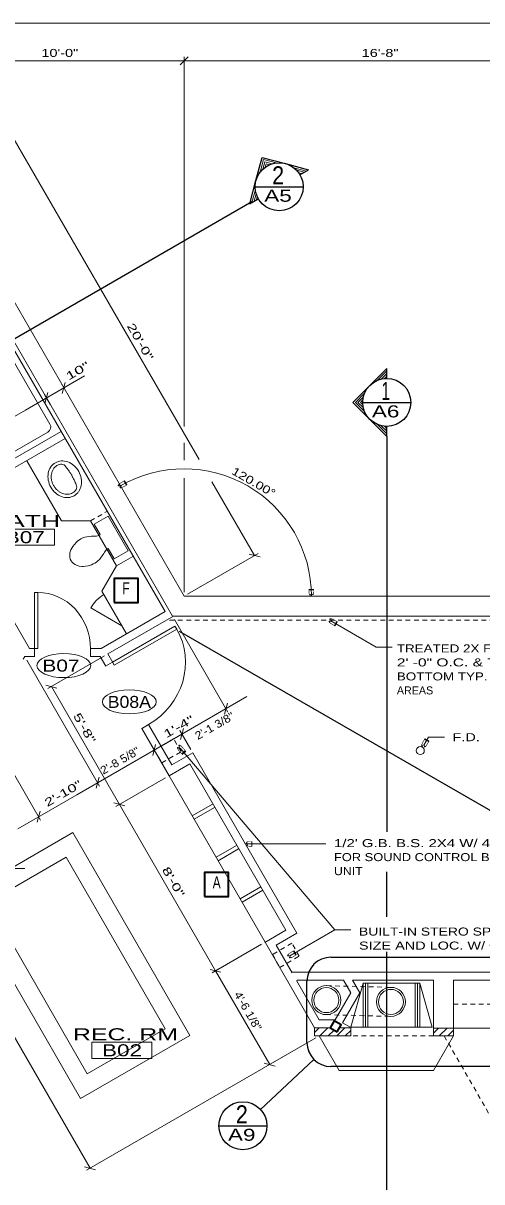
# Model space of a CAD drawing. Extents: x 7 to 126, y 6 to 93.
# Drawn here: x 37.51 to 56.6, y 44.6 to 92.85 of the extents above; entities that cross this region are included whole.
import ezdxf
from ezdxf.enums import TextEntityAlignment as Align

# ---------------------------------------------------------------- set-up
doc = ezdxf.new("R2010")
doc.units = 0
doc.header["$LTSCALE"] = 0.13
doc.linetypes.add('SHORT_DASHED', pattern=[2.7, 1.5, -1.2])
for name, color, linetype, lineweight in [('12', 7, 'Continuous', 35), ('14', 7, 'Continuous', 13), ('15', 7, 'Continuous', 13), ('17', 7, 'Continuous', 13), ('22', 7, 'SHORT_DASHED', 13), ('24', 7, 'Continuous', 13), ('30', 7, 'Continuous', 13), ('34', 7, 'Continuous', 13), ('35', 7, 'Continuous', 13), ('37', 7, 'SHORT_DASHED', 13), ('38', 7, 'Continuous', 13), ('40', 7, 'Continuous', 13), ('42', 7, 'Continuous', 13), ('45', 7, 'Continuous', 13), ('50', 7, 'Continuous', 13), ('53', 7, 'Continuous', 13), ('55', 7, 'Continuous', 13), ('56', 7, 'Continuous', 13), ('7', 7, 'Continuous', 13)]:
    doc.layers.add(name, color=color, linetype=linetype, lineweight=lineweight)

msp = doc.modelspace()

# ---------------------------------------------------------------- linework, layer by layer
at = {"layer": '12'}
msp.add_lwpolyline([(50.5834, 50.8466), (50.7501, 51.1353), (50.4615, 51.302), (50.2948, 51.0133)], close=True, dxfattribs=at)
msp.add_lwpolyline([(50.5834, 50.8466), (50.7501, 51.1353), (50.4615, 51.302), (50.2948, 51.0133)], close=True, dxfattribs=at)
msp.add_lwpolyline([(50.5834, 50.8466), (50.7501, 51.1353), (50.4615, 51.302), (50.2948, 51.0133)], close=True, dxfattribs=at)
msp.add_lwpolyline([(50.5834, 50.8466), (50.7501, 51.1353), (50.4615, 51.302), (50.2948, 51.0133)], close=True, dxfattribs=at)
at = {"layer": '14'}
msp.add_lwpolyline([(115.8724, 34.3511), (77.539, 34.3511), (75.8724, 37.2379), (59.2057, 37.2379), (57.539, 34.3511), (40.8724, 34.3511), (16.7057, 76.209), (22.539, 86.3127), (34.2057, 86.3127), (44.2057, 68.9922), (60.8724, 68.9922)], dxfattribs=at)
at = {"layer": '15'}
msp.add_lwpolyline([(23.2126, 85.4793), (33.7246, 85.4793), (43.7246, 68.1588), (60.3912, 68.1588), (63.7246, 62.3853)], dxfattribs=at)
at = {"layer": '17'}
for points in [[(37.9761, 66.811), (38.122, 66.811), (38.122, 69.1444), (37.9761, 69.1444)], [(41.231, 66.2432), (41.3039, 66.1169), (43.902, 67.6169), (43.8291, 67.7432)]]:
    msp.add_lwpolyline(points, close=True, dxfattribs=at)
for centre, major_axis, ratio, start_param, end_param in [((38.122, 66.811), (0, 2.3333), 0.9375, 4.7123888, 6.2831852), ((41.3039, 66.1169), (2.5981, 1.5), 0.951389, 4.712389, 6.2831853)]:
    msp.add_ellipse(centre, major_axis=major_axis, ratio=ratio, start_param=start_param, end_param=end_param, dxfattribs=at)
at = {"layer": '22'}
msp.add_line((55.0345, 50.6771), (61.6389, 39.2379), dxfattribs=at)
at = {"layer": '24'}
msp.add_line((36.5897, 80.1835), (43.423, 68.3478), dxfattribs=at)
at = {"layer": '24', "linetype": 'SHORT_DASHED'}
msp.add_line((60.295, 67.9922), (43.4737, 67.9922), dxfattribs=at)
at = {"layer": '30'}
for p, q in [((36.9987, 78.9763), (38.6238, 76.1617)), ((38.5323, 75.8202), (37.0889, 74.9869))]:
    msp.add_line(p, q, dxfattribs=at)
msp.add_lwpolyline([(41.0446, 72.3211), (40.4673, 71.9877), (40.7173, 71.5547), (40.6555, 71.516), (40.5644, 71.4913), (40.4501, 71.4966), (40.3605, 71.4934), (40.2543, 71.4824), (40.1564, 71.4642), (40.0776, 71.4445), (39.9984, 71.416), (39.913, 71.378), (39.8509, 71.3381), (39.7873, 71.291), (39.7118, 71.2243), (39.6407, 71.1488), (39.5749, 71.0632), (39.5303, 70.9901), (39.4976, 70.9221), (39.4575, 70.7905), (39.4482, 70.6755), (39.4537, 70.6152), (39.4727, 70.5385), (39.5047, 70.4677), (39.5475, 70.4085), (39.6057, 70.3525), (39.6758, 70.3051), (39.752, 70.2706), (39.8348, 70.2476), (39.9475, 70.2327), (40.0095, 70.232), (40.1094, 70.2392), (40.2096, 70.2579), (40.2753, 70.2754), (40.3494, 70.3011), (40.4229, 70.3324), (40.4897, 70.3662), (40.5575, 70.4128), (40.6224, 70.4671), (40.6807, 70.5255), (40.732, 70.5813), (40.8258, 70.7096), (40.8667, 70.775), (40.8998, 70.8317), (40.9491, 70.8911), (40.9783, 70.9318), (41.0506, 70.9774), (41.3006, 70.5443), (41.8779, 70.8777)], close=True, dxfattribs=at)
for centre, radius, start, end in [((38.4073, 76.0367), 0.25, 300.00068, 30.00067), ((39.2296, 73.9899), 0.6869, 145.81242, 169.51991), ((39.1285, 74.0586), 0.5645, 119.62087, 145.81234), ((39.1845, 74.0156), 0.5001, 133.16969, 146.34099), ((39.0531, 74.1557), 0.308, 116.36309, 133.16961), ((39.1285, 74.0586), 0.5645, 93.42928, 119.62076), ((39.2065, 73.8462), 0.6534, 106.0719, 116.36309), ((39.1251, 74.1288), 0.3594, 92.17984, 106.07193), ((39.1358, 73.9365), 0.6869, 69.72172, 93.42921), ((39.1509, 73.4495), 1.0391, 91.91307, 92.17961), ((39.1027, 74.2763), 0.2122, 30.85374, 86.34916), ((37.8748, 73.1946), 1.8455, 36.84686, 40.17264), ((39.0975, 73.833), 0.7973, 48.85017, 69.72174), ((39.0051, 73.7272), 0.9377, 29.62085, 48.85013), ((39.3382, 73.9698), 0.7973, 169.51989, 190.39146), ((39.4763, 73.9951), 0.9377, 190.3915, 209.62078), ((39.3784, 73.9694), 0.7022, 171.03129, 180.85676), ((39.339, 73.9689), 0.6627, 180.85676, 190.97092), ((39.2141, 73.9954), 0.5359, 158.6742, 171.03122), ((39.4677, 73.9938), 0.7938, 190.97086, 200.35226), ((39.2161, 73.9946), 0.538, 146.34097, 158.67423), ((37.7139, 73.074), 2.0465, 32.31847, 36.84686), ((32.8239, 69.9805), 7.8329, 31.47847, 32.31848), ((38.1381, 73.2343), 1.6017, 29.62081, 31.47847), ((38.1381, 73.2343), 1.6017, 27.76316, 29.62081), ((32.6242, 70.3317), 7.8329, 26.92315, 27.76316), ((37.7835, 72.9517), 2.0465, 22.39476, 26.92315), ((39.0051, 73.7272), 0.9377, 10.3915, 29.62078), ((39.1432, 73.7526), 0.7973, 349.51989, 10.39146), ((39.4763, 73.9951), 0.9377, 209.62085, 228.85013), ((39.4858, 74.0006), 0.8132, 200.35224, 209.62084), ((39.4858, 74.0006), 0.8132, 209.62078, 218.88939), ((39.4707, 73.9884), 0.7938, 218.88936, 228.27077), ((39.3835, 73.8905), 0.6627, 228.27071, 238.38486), ((39.2104, 73.8394), 0.6534, 302.87853, 313.16973), ((39.353, 73.6637), 0.5645, 299.62087, 325.81234), ((39.4115, 73.625), 0.3594, 313.1697, 327.06178), ((37.9694, 73.0283), 1.8455, 19.06899, 22.39476), ((38.8411, 73.9946), 1.0391, 327.06202, 327.32856), ((39.5268, 73.5303), 0.2122, 332.89247, 28.38789), ((39.2518, 73.7325), 0.6869, 325.81242, 349.51991), ((39.3839, 73.8894), 0.7973, 228.85017, 249.72174), ((39.4041, 73.9241), 0.7022, 238.38487, 248.21034), ((39.3456, 73.7859), 0.6869, 249.72172, 273.42921), ((39.3424, 73.7697), 0.5359, 248.21041, 260.56743), ((39.3428, 73.7718), 0.538, 260.5674, 272.90066), ((39.3447, 73.7339), 0.5001, 272.90064, 286.07194), ((39.353, 73.6637), 0.5645, 273.42928, 299.62076), ((39.3979, 73.5494), 0.308, 286.07202, 302.87854)]:
    msp.add_arc(centre, radius, start, end, dxfattribs=at)
at = {"layer": '34'}
for points in [[(39.5727, 59.145), (35.0261, 56.5199), (39.9011, 48.0762), (44.4477, 50.7012)], [(39.2982, 58.1204), (36.0506, 56.2454), (40.1756, 49.1007), (43.4232, 50.9757)]]:
    msp.add_lwpolyline(points, close=True, dxfattribs=at)
at = {"layer": '35'}
for p, q in [((39.1014, 72.1256), (37.659, 74.6238)), ((39.1014, 72.1256), (40.3082, 72.1256)), ((41.3904, 70.2512), (40.3082, 72.1256)), ((41.3904, 70.2512), (42.0793, 70.6489)), ((41.3904, 70.2512), (40.787, 69.206)), ((40.787, 69.206), (41.8176, 67.4209)), ((41.6223, 67.7593), (40.3232, 68.5093)), ((43.5811, 61.5109), (47.5778, 54.5885)), ((44.5429, 59.8451), (45.3934, 60.3362)), ((44.6262, 59.7008), (45.4768, 60.1918)), ((45.5406, 58.117), (46.3954, 58.6105)), ((45.624, 57.9726), (46.4788, 58.4661)), ((46.5384, 56.3888), (47.4062, 56.8898)), ((46.6217, 56.2445), (47.4895, 56.7455)), ((55.4271, 51), (59.1651, 51))]:
    msp.add_line(p, q, dxfattribs=at)
at = {"layer": '35', "linetype": 'SHORT_DASHED'}
for p, q in [((40.3082, 72.1256), (40.9971, 72.5233)), ((55.4271, 52), (59.1651, 52))]:
    msp.add_line(p, q, dxfattribs=at)
at = {"layer": '35'}
msp.add_arc((41.6223, 67.7593), 1.5, 120.0003, 150.00007, dxfattribs=at)
at = {"layer": '37'}
for points in [[(42.9678, 62.5904), (43.2787, 62.052), (44.0846, 62.5174), (43.7738, 63.0558)], [(47.8854, 54.0729), (48.1963, 53.5345), (49.0022, 53.9998), (48.6914, 54.5382)]]:
    msp.add_lwpolyline(points, close=True, dxfattribs=at)
at = {"layer": '38', "linetype": 'SHORT_DASHED'}
for p, q in [((50.1455, 52.7727), (52.8351, 52.7014)), ((50.1135, 51.5648), (52.8031, 51.4934))]:
    msp.add_line(p, q, dxfattribs=at)
at = {"layer": '38'}
for p, q in [((51.6649, 52.8703), (51.6649, 51.0376)), ((51.7598, 51.037), (51.7598, 52.8727)), ((51.8547, 51.037), (51.8547, 52.8727)), ((53.8293, 51.037), (53.8293, 52.8727)), ((53.9242, 51.037), (53.9242, 52.8727)), ((54.0191, 52.8703), (54.5347, 51.037)), ((54.0191, 52.8703), (54.0191, 51.0376))]:
    msp.add_line(p, q, dxfattribs=at)
msp.add_lwpolyline([(54.5347, 51.037), (51.1493, 51.037), (51.6649, 52.8703), (54.0191, 52.8703)], dxfattribs=at)
for centre, radius in [((50.1295, 52.1688), 0.6042), ((50.1295, 52.1688), 0.5208), ((52.8191, 52.0974), 0.6042), ((52.8191, 52.0974), 0.5208)]:
    msp.add_circle(centre, radius, dxfattribs=at)
at = {"layer": '40', "lineweight": 25}
for p, q in [((48.4255, 87.0076), (49.3914, 86.7488)), ((49.0327, 86.5417), (49.3914, 86.7488)), ((46.9419, 85.3346), (47.2007, 86.3005)), ((47.1667, 86.0417), (49.1667, 86.0417)), ((47.0263, 85.4148), (22.9019, 71.4604)), ((46.9419, 85.3346), (47.3006, 85.5417)), ((51.9387, 77.7696), (52.6458, 78.4767)), ((52.6458, 78.0625), (52.6458, 78.4767)), ((51.6458, 77.0625), (53.6458, 77.0625)), ((52.6458, 75.6483), (51.9387, 76.3554)), ((52.6458, 75.6483), (52.6458, 76.0625)), ((52.6458, 75.6483), (52.6458, 59.1771)), ((44.0104, 67.5385), (58.5628, 59.1367)), ((52.6458, 55.6354), (52.6458, 57.5104)), ((52.6458, 30.5373), (52.6458, 54.1771)), ((50.3229, 53.9583), (59.4896, 53.9583)), ((49.3229, 50.4062), (49.3229, 52.9583)), ((47.3874, 47.6197), (49.6158, 49.6991)), ((59.4896, 49.4062), (50.3229, 49.4062)), ((45.6562, 46.9375), (47.6562, 46.9375))]:
    msp.add_line(p, q, dxfattribs=at)
at = {"layer": '40'}
for p, q in [((48.7731, 86.8368), (49.2996, 86.6957)), ((48.8955, 86.7264), (49.2077, 86.6427)), ((48.9777, 86.6267), (49.1158, 86.5897)), ((47.0338, 85.3876), (47.1748, 85.9141)), ((47.1256, 85.4406), (47.2093, 85.7528)), ((47.2175, 85.4937), (47.2545, 85.6318)), ((52.2604, 77.9852), (52.6458, 78.3707)), ((52.4173, 78.036), (52.6458, 78.2646)), ((52.5447, 78.0574), (52.6458, 78.1585)), ((52.6458, 75.7543), (52.2604, 76.1398)), ((52.6458, 75.8604), (52.4173, 76.089)), ((52.6458, 75.9665), (52.5447, 76.0676)), ((32.3958, 57.6458), (37.5833, 57.6458))]:
    msp.add_line(p, q, dxfattribs=at)
at = {"layer": '40', "lineweight": 25}
for points in [[(47.2007, 86.3005), (47.4596, 87.2664), (48.4255, 87.0076)], [(51.9387, 76.3554), (51.2316, 77.0625), (51.9387, 77.7696)]]:
    msp.add_lwpolyline(points, dxfattribs=at)
at = {"layer": '40'}
for points in [[(47.3715, 86.6481), (47.5126, 87.1746), (48.0391, 87.0335)], [(47.482, 86.7705), (47.5656, 87.0827), (47.8778, 86.999)], [(47.5816, 86.8527), (47.6187, 86.9908), (47.7568, 86.9538)], [(51.7231, 76.6771), (51.3377, 77.0625), (51.7231, 77.4479)], [(51.6723, 76.8339), (51.4438, 77.0625), (51.6723, 77.2911)], [(51.651, 76.9614), (51.5498, 77.0625), (51.651, 77.1636)]]:
    msp.add_lwpolyline(points, dxfattribs=at)
at = {"layer": '40', "lineweight": 35}
for points in [[(41.2917, 68.7292), (42.2917, 68.7292), (42.2917, 69.7292), (41.2917, 69.7292)], [(45.0521, 56.4792), (46.0521, 56.4792), (46.0521, 57.4792), (45.0521, 57.4792)]]:
    msp.add_lwpolyline(points, close=True, dxfattribs=at)
at = {"layer": '40', "lineweight": 25}
for centre in [(48.1667, 86.0417), (52.6458, 77.0625), (46.6562, 46.9375)]:
    msp.add_circle(centre, 1, dxfattribs=at)
for centre, start, end in [((50.3229, 52.9583), 90, 180), ((50.3229, 50.4062), 180, 270)]:
    msp.add_arc(centre, 1, start, end, dxfattribs=at)
at = {"layer": '42'}
for centre in [(39.2036, 66.1007), (41.9292, 64.5895)]:
    msp.add_ellipse(centre, major_axis=(1.1204, 0), ratio=0.446291, dxfattribs=at)
at = {"layer": '45'}
for points in [[(36.3283, 71.1124), (38.8135, 71.1124), (38.8135, 71.783), (36.3283, 71.783)], [(40.3743, 49.7437), (42.8595, 49.7437), (42.8595, 50.4144), (40.3743, 50.4144)]]:
    msp.add_lwpolyline(points, close=True, dxfattribs=at)
at = {"layer": '50'}
for p, q in [((121.0473, 92.8542), (16.7057, 92.8542)), ((34.2057, 91.2812), (44.2057, 91.2812)), ((44.039, 91.1146), (44.3724, 91.4479)), ((44.039, 91.1146), (44.3724, 91.4479)), ((44.2057, 91.4479), (44.2057, 76.0625)), ((44.2057, 91.2812), (60.8724, 91.2812)), ((44.2057, 91.2812), (44.2057, 91.1146)), ((37.1408, 88.0073), (44.8297, 74.6898)), ((37.6129, 76.7445), (40.0667, 78.1612)), ((39.1224, 77.7967), (39.1173, 77.8055)), ((39.1396, 77.4335), (39.2616, 77.8888)), ((33.4271, 74.3278), (38.479, 77.2445)), ((38.6412, 76.9634), (38.3956, 77.3888)), ((38.54, 77.4722), (38.418, 77.0168)), ((38.54, 77.4722), (38.418, 77.0168)), ((44.2057, 74.6562), (44.2057, 75.375)), ((44.2057, 69.1588), (44.2057, 73.9062)), ((47.1408, 70.6868), (45.37, 73.7539)), ((44.35, 69.0755), (47.2852, 70.7701)), ((47.3685, 70.6257), (46.9132, 70.7478)), ((43.8079, 68.0145), (46.031, 64.1639)), ((37.6589, 66.3315), (40.6905, 61.0806)), ((40.8921, 66.5017), (38.5395, 65.1434)), ((38.4561, 65.2877), (38.9115, 65.1657)), ((38.6838, 65.2267), (41.5172, 60.3193)), ((43.2502, 62.7508), (46.8137, 64.8082)), ((45.8867, 64.0805), (46.0087, 64.5359)), ((36.0231, 63.4981), (38.2368, 59.6639)), ((42.0955, 62.0841), (44.1162, 63.2508)), ((44.4858, 62.6106), (44.0329, 63.3951)), ((44.176, 63.1472), (44.0329, 63.3951)), ((44.0552, 63.0231), (44.1772, 63.4785)), ((44.1772, 63.4785), (44.0552, 63.0231)), ((39.7412, 60.7249), (43.8275, 63.0841)), ((42.9294, 62.6396), (42.8782, 62.7285)), ((42.9005, 62.3565), (43.0225, 62.8118)), ((43.0225, 62.8118), (42.9005, 62.3565)), ((37.2874, 59.3082), (41.4732, 61.7249)), ((40.5462, 60.9972), (40.6682, 61.4526)), ((40.6682, 61.4526), (40.5462, 60.9972)), ((43.4368, 61.4276), (41.3728, 60.2359)), ((31.2053, 60.909), (40.2936, 45.1677)), ((41.7448, 60.2583), (41.2895, 60.3803)), ((41.2895, 60.3803), (41.7448, 60.2583)), ((41.5172, 60.3193), (45.5172, 53.3911)), ((38.2144, 60.0359), (38.0924, 59.5806)), ((47.4368, 54.4994), (45.3728, 53.3077)), ((45.7448, 53.3301), (45.2895, 53.4521)), ((45.2895, 53.4521), (45.7448, 53.3301)), ((45.2895, 53.4521), (45.7448, 53.3301)), ((45.5172, 53.3911), (45.6615, 53.4744)), ((45.5172, 53.3911), (47.7721, 49.4854)), ((49.6917, 50.5938), (40.1493, 45.0844)), ((49.6917, 50.5938), (47.6277, 49.4021)), ((47.9998, 49.4244), (47.5444, 49.5464)), ((40.5213, 45.1067), (40.0659, 45.2287))]:
    msp.add_line(p, q, dxfattribs=at)
for points in [[(50.3125, 67.9688), (52.2069, 66.875), (52.8736, 66.875)], [(54.1875, 62.7812), (54.383, 63.1199), (55.0497, 63.1199)], [(44.0417, 62.6562), (50.4883, 55.0982), (51.1549, 55.0982)], [(46.7604, 58.6771), (49.4479, 58.6771), (50.1146, 58.6771)], [(48.6042, 54.0104), (50.4883, 55.0982), (51.1549, 55.0982)]]:
    msp.add_lwpolyline(points, dxfattribs=at)
msp.add_circle((54.0417, 62.5625), 0.1667, dxfattribs=at)
msp.add_arc((44.2057, 68.9922), 5.3029, 0, 119.99998, dxfattribs=at)
at = {"layer": '53'}
for p, q in [((31.6822, 77.3502), (37.7681, 66.8092)), ((36.4378, 74.3223), (39.0902, 75.8537)), ((36.6045, 74.0337), (39.2569, 75.565)), ((43.423, 68.3478), (40.758, 66.8091)), ((43.7623, 68.1588), (41.0365, 66.585)), ((37.7681, 66.8092), (37.9871, 66.8092)), ((37.9761, 66.811), (37.9761, 66.4684)), ((40.3095, 66.811), (40.3095, 66.4758)), ((40.758, 66.8091), (40.3095, 66.8091)), ((37.5756, 66.4758), (37.511, 66.364)), ((37.5756, 66.4758), (37.9615, 66.4758)), ((40.7146, 66.4758), (40.3095, 66.4758)), ((40.7146, 66.4758), (40.9459, 66.0753)), ((41.231, 66.2432), (40.9329, 66.0711)), ((41.0365, 66.585), (41.2398, 66.2329)), ((42.731, 63.6451), (42.4329, 63.473)), ((42.4444, 63.4797), (43.5811, 61.5109)), ((42.7331, 63.6464), (43.7031, 61.9662)), ((44.5692, 62.4662), (43.7031, 61.9662)), ((48.9025, 54.9607), (44.5692, 62.4662)), ((44.4472, 62.0109), (43.5811, 61.5109)), ((48.4472, 55.0827), (44.4472, 62.0109)), ((48.4472, 55.0827), (47.5695, 54.576)), ((49.6436, 51.0104), (47.5811, 54.5827)), ((48.9025, 54.9607), (48.0365, 54.4607)), ((48.7016, 53.3086), (48.0365, 54.4607)), ((48.7237, 53.3333), (51.0331, 53.3333)), ((48.7237, 53.3333), (54.9271, 53.3333)), ((54.9271, 53.3333), (60.5417, 53.3333)), ((49.8352, 51.3452), (48.8889, 52.9842)), ((48.9162, 53), (50.8407, 53)), ((51.2256, 53), (51.5287, 52.4751)), ((51.2256, 53), (54.5938, 53)), ((54.5938, 50.6771), (54.5938, 53)), ((51.1437, 52.4751), (50.4914, 51.3452)), ((51.5287, 52.4751), (50.8093, 51.2292)), ((49.8352, 51.3452), (50.4914, 51.3452)), ((50.7656, 50.6771), (51.1458, 50.6771)), ((55.4271, 50.6771), (54.5938, 50.6771))]:
    msp.add_line(p, q, dxfattribs=at)
at = {"layer": '53', "linetype": 'SHORT_DASHED'}
for p, q in [((51.1458, 50.6771), (49.8361, 50.6771)), ((54.5938, 50.6771), (51.1493, 50.6771))]:
    msp.add_line(p, q, dxfattribs=at)
at = {"layer": '53'}
for points in [[(48.9162, 53), (50.8407, 53), (51.1437, 52.4751)], [(55.4271, 50.6771), (55.4271, 53), (59.1651, 53)], [(50.8093, 51.2292), (51.1493, 51.0329), (51.1493, 50.6867)]]:
    msp.add_lwpolyline(points, dxfattribs=at)
at = {"layer": '55'}
for p, q in [((49.8361, 50.6771), (50.6694, 49.2337)), ((55.4271, 50.6771), (54.5938, 49.2337)), ((54.5938, 49.2337), (50.6694, 49.2337))]:
    msp.add_line(p, q, dxfattribs=at)
at = {"layer": '56'}
for p, q in [((49.6436, 50.8204), (49.8345, 51.0113)), ((49.8539, 50.6771), (50.1896, 51.0129)), ((50.2074, 50.6771), (50.4526, 50.9222)), ((50.561, 50.6771), (50.8943, 51.0104)), ((50.9145, 50.6771), (51.1482, 50.9108)), ((54.5938, 50.7914), (54.8024, 51)), ((54.833, 50.6771), (55.1559, 51)), ((55.1866, 50.6771), (55.4271, 50.9176))]:
    msp.add_line(p, q, dxfattribs=at)
for points in [[(49.6436, 51.0104), (49.6436, 50.6771), (51.1458, 50.6771), (51.1493, 51.0104), (50.678, 51.0104), (50.5834, 50.8466), (50.2948, 51.0133)], [(54.5938, 50.6771), (55.4271, 50.6771), (55.4271, 51), (54.5938, 51)]]:
    msp.add_lwpolyline(points, close=True, dxfattribs=at)
at = {"layer": '7'}
msp.add_lwpolyline([(115.8724, 34.3511), (77.539, 34.3511), (75.8724, 37.2379), (59.2057, 37.2379), (57.539, 34.3511), (40.8724, 34.3511), (16.7057, 76.209), (22.539, 86.3127), (34.2057, 86.3127), (44.2057, 68.9922), (60.8724, 68.9922), (64.2057, 63.2187), (65.039, 63.2187), (75.039, 63.2187), (80.039, 71.8789), (96.7057, 71.8789), (98.789, 75.4873), (113.4884, 75.4873), (121.0473, 51.0685)], dxfattribs=at)

# ---------------------------------------------------------------- texts
at = {"layer": '40'}
for s, height, width, p in [('2', 0.75, 0.9, (48.1229, 86.1427)), ('A5 ', 0.5, 1.4, (48.249, 85.4167)), ('1', 0.75, 0.65, (52.6021, 77.1636)), ('A6 ', 0.5, 1.4, (52.7281, 76.4375)), ('2', 0.75, 0.9, (46.6125, 47.0386)), ('A9 ', 0.5, 1.4, (46.7385, 46.3125))]:
    msp.add_text(s, height=height, dxfattribs=dict(at, width=width)).set_placement(p, align=Align.CENTER)
at = {"layer": '40', "width": 0.75}
for s, p in [('F', (41.6373, 69.0712)), ('A', (45.3977, 56.8212))]:
    msp.add_text(s, height=0.5, dxfattribs=at).set_placement(p)
at = {"layer": '42'}
for s, width, p in [('B07 ', 1.3, (39.2036, 65.8507)), ('B08A', 1.1, (41.9292, 64.3395))]:
    msp.add_text(s, height=0.5, dxfattribs=dict(at, width=width)).set_placement(p, align=Align.CENTER)
at = {"layer": '45'}
for s, width, p in [('        BATH        ', 1.65, (37.5783, 71.8664)), (' B07 ', 1.4, (37.5783, 71.1997)), ('       REC. RM      ', 1.55, (41.6243, 50.4977)), (' B02 ', 1.4, (41.6243, 49.831))]:
    msp.add_text(s, height=0.5, dxfattribs=dict(at, width=width)).set_placement(p, align=Align.CENTER)
at = {"layer": '50'}
for s, width, p in [('10\'-0"', 1.35, (38.2687, 91.4479)), ('16\'-8"', 1.35, (51.602, 91.4479)), ('TREATED 2X FURING @ ', 1.25, (53.0658, 66.6506)), ('2\' -0" O.C. & TOP & ', 1.45, (53.0658, 66.0673)), ('BOTTOM TYP. UNFINISHED', 1.25, (53.0658, 65.484)), ('F.D.', 1.35, (55.383, 62.9532)), ('1/2\' G.B. B.S. 2X4 W/ 4" BATT INSUL. ', 1.4, (50.4479, 58.5417)), ('FOR SOUND CONTROL BE HIND HEATING ', 1.2, (50.4479, 57.9583)), ('UNIT', 1.15, (50.4479, 57.375)), ('BUILT-IN STERO SPEAKER VERIFY ', 1.3, (51.4883, 54.8586)), ('SIZE AND LOC. W/ OWNER 2 LOC. ', 1.35, (51.4883, 54.2753))]:
    msp.add_text(s, height=0.3333, dxfattribs=dict(at, width=width)).set_placement(p)
for s, rotation, width, p in [('20\'-0"', 300, 1.5, (41.8167, 80.2418)), ('10"', 30, 1.6, (39.406, 77.9722)), ('120.00°', 330, 1.3, (46.1555, 74.1)), ('2\'-1 3/8"', 30, 1.1, (44.785, 63.0013)), ('5\'-8"', 300, 1.55, (39.5778, 64.0117)), ('1\'-4"', 30, 1.55, (43.4736, 63.0722)), ('2\'-8 5/8"', 30, 1.1, (40.8447, 61.5545)), ('2\'-10"', 30, 1.5, (38.5172, 60.2107)), ('8\'-0"', 300, 1.55, (43.2757, 57.6068)), ('4\'-6 1/8"', 300, 1.1, (46.2785, 52.4058))]:
    msp.add_text(s, height=0.3333, rotation=rotation, dxfattribs=dict(at, width=width)).set_placement(p)
for rotation, width, p in [(210, 2.35, (41.3876, 73.6166)), (270, 1.7, (49.3974, 68.9922)), (150, 2.35, (50.2569, 68.1291)), (130.462, 2.65, (44.0032, 62.8726)), (240, 2.35, (54.0271, 62.7257)), (180, 1.7, (46.7604, 58.7882)), (210, 2.35, (48.4375, 54.0425))]:
    msp.add_text('B', height=0.2222, rotation=rotation, dxfattribs=dict(at, width=width)).set_placement(p, align=Align.RIGHT)
msp.add_text('AREAS', height=0.3333, dxfattribs=at).set_placement((53.0658, 64.9006))

doc.saveas('drawing.dxf')
